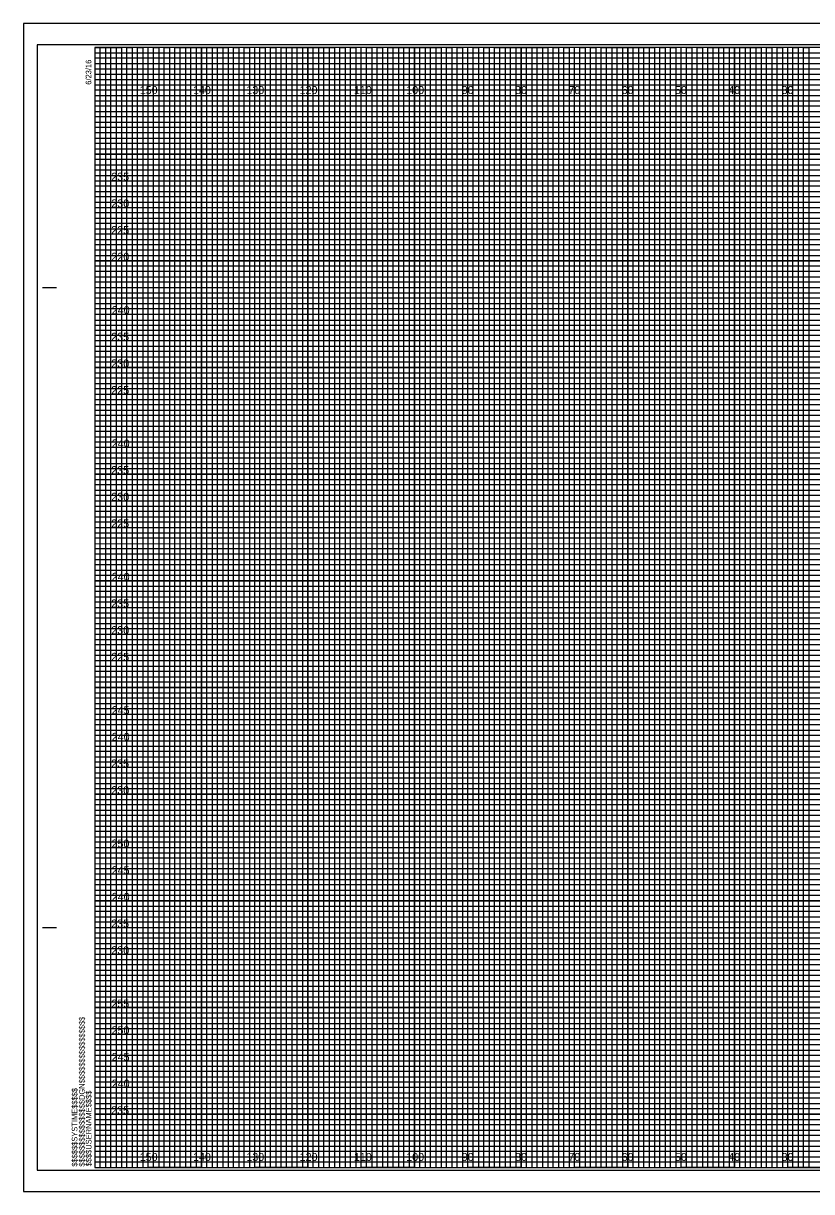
# Model space of a CAD drawing. Extents: x -13 to 323, y -5 to 434.
# Drawn here: x -13.4 to 134.5, y -4.5 to 214.5 of the extents above; entities that cross this region are included whole.
import ezdxf

# ---------------------------------------------------------------- set-up
doc = ezdxf.new("R2010")
doc.units = 0
for name, color, linetype in [('Prop XS Elevation Labels', 7, 'Continuous'), ('Prop XS Offset Labels', 7, 'Continuous'), ('Sheet Cross Section CELL', 7, 'Continuous'), ('Sheet Cross Section Grid Major CELL', 7, 'Continuous'), ('Sheet Cross Section Grid Middle CELL', 7, 'Continuous'), ('Sheet Cross Section Grid Minor 1 CELL', 7, 'Continuous'), ('Sheet Cross Section Grid Minor 2 CELL', 7, 'Continuous'), ('Sheet Cutting Line CELL', 7, 'Continuous'), ('Sheet DOT Grid CELL', 7, 'Continuous'), ('Sheet Plot Border Inside CELL', 7, 'Continuous'), ('Sheet Plot Border Outside CELL', 7, 'Continuous')]:
    doc.layers.add(name, color=color, linetype=linetype)

msp = doc.modelspace()

# ---------------------------------------------------------------- linework, layer by layer
at = {"layer": 'Sheet Cross Section CELL'}
for p, q in [((-9.8, 165), (-7.3, 165)), ((-9.7, 165), (-7.2, 165)), ((-9.8, 45), (-7.3, 45)), ((-9.7, 45), (-7.2, 45)), ((0, 0), (0, 0)), ((0, 0), (0, 0)), ((0, 0), (0, 0)), ((0, 0), (0, 0)), ((0, 0), (0, 0)), ((0, 0), (0, 0)), ((0, 0), (0, 0))]:
    msp.add_line(p, q, dxfattribs=at)
msp.add_lwpolyline([(320, 210), (0, 210), (0, 0), (320, 0)], close=True, dxfattribs=at)
at = {"layer": 'Sheet Cross Section Grid Major CELL'}
for p, q in [((10, 210), (0, 210)), ((10, 0), (10, 210)), ((30, 210), (20, 210)), ((20, 210), (20, 0)), ((30, 0), (30, 210)), ((50, 210), (40, 210)), ((40, 210), (40, 0)), ((50, 0), (50, 210)), ((70, 210), (60, 210)), ((60, 210), (60, 0)), ((70, 0), (70, 210)), ((90, 210), (80, 210)), ((80, 210), (80, 0)), ((90, 0), (90, 210)), ((110, 210), (100, 210)), ((100, 210), (100, 0)), ((110, 0), (110, 210)), ((130, 210), (120, 210)), ((120, 210), (120, 0)), ((130, 0), (130, 210)), ((20, 0), (10, 0)), ((40, 0), (30, 0)), ((60, 0), (50, 0)), ((80, 0), (70, 0)), ((100, 0), (90, 0)), ((120, 0), (110, 0)), ((140, 0), (130, 0))]:
    msp.add_line(p, q, dxfattribs=at)
for points in [[(0, 200), (320, 200), (320, 190), (0, 190)], [(0, 180), (320, 180), (320, 170), (0, 170)], [(0, 160), (320, 160), (320, 150), (0, 150)], [(0, 140), (320, 140), (320, 130), (0, 130)], [(0, 120), (320, 120), (320, 110), (0, 110)], [(0, 100), (320, 100), (320, 90), (0, 90)], [(0, 80), (320, 80), (320, 70), (0, 70)], [(0, 60), (320, 60), (320, 50), (0, 50)], [(0, 40), (320, 40), (320, 30), (0, 30)], [(0, 20), (320, 20), (320, 10), (0, 10)]]:
    msp.add_lwpolyline(points, dxfattribs=at)
at = {"layer": 'Sheet Cross Section Grid Middle CELL'}
for points in [[(0, 210), (5, 210), (5, 0), (15, 0), (15, 210), (25, 210), (25, 0), (35, 0), (35, 210), (45, 210), (45, 0), (55, 0), (55, 210), (65, 210), (65, 0), (75, 0), (75, 210), (85, 210), (85, 0), (95, 0), (95, 210), (105, 210), (105, 0), (115, 0), (115, 210), (125, 210), (125, 0), (135, 0)], [(0, 205), (275, 205)], [(0, 185), (320, 185), (320, 195), (0, 195)], [(0, 165), (320, 165), (320, 175), (0, 175)], [(0, 145), (320, 145), (320, 155), (0, 155)], [(0, 125), (320, 125), (320, 135), (0, 135)], [(0, 105), (320, 105), (320, 115), (0, 115)], [(0, 85), (320, 85), (320, 95), (0, 95)], [(0, 65), (320, 65), (320, 75), (0, 75)], [(0, 45), (320, 45), (320, 55), (0, 55)], [(0, 25), (320, 25), (320, 35), (0, 35)], [(0, 5), (320, 5), (320, 15), (0, 15)]]:
    msp.add_lwpolyline(points, dxfattribs=at)
at = {"layer": 'Sheet Cross Section Grid Minor 1 CELL'}
for p, q in [((0, 209), (260, 209)), ((260, 207.98), (0, 207.98)), ((0, 207.98), (0, 207)), ((0, 207), (260, 207)), ((260, 205.89), (0, 205.89)), ((0, 205.89), (0, 204)), ((0, 204), (320, 204))]:
    msp.add_line(p, q, dxfattribs=at)
for points in [[(0, 203), (270, 203), (320, 203), (320, 202), (0, 202)], [(0, 201), (320, 201), (320, 199), (0, 199)], [(0, 198), (320, 198), (320, 197), (0, 196.98)], [(0, 196), (320, 196), (320, 194), (0, 194)], [(0, 193), (320, 193), (320, 192), (0, 192)], [(0, 191), (320, 191), (320, 189), (0, 189)], [(0, 188), (320, 188), (320, 187), (0, 187)], [(0, 186), (320, 186), (320, 184), (0, 184)], [(0, 183), (320, 183), (320, 182), (0, 182)], [(0, 181), (320, 181), (320, 179), (0, 179)], [(0, 178), (320, 178), (320, 177), (0, 177)], [(0, 176), (320, 176), (320, 173.95), (320, 173), (320, 172), (0, 172)], [(0, 174), (320, 174), (320, 173), (0, 173)], [(0, 171), (320, 171), (320, 169), (0, 169.03)], [(0, 169.03), (320, 169), (320, 168), (0, 168)], [(0, 167), (320, 167), (320, 166), (0, 166)], [(0, 164), (320, 164), (320, 163), (0, 163)], [(0, 162), (320, 162), (320, 161), (0, 161)], [(-0.07, 158.89), (320, 158.89), (320, 157.88), (-0.07, 157.88)], [(0, 157), (320, 157), (320, 156), (0, 156)], [(0, 154), (320, 154), (320, 153), (0, 153)], [(0, 152), (320, 152), (320, 151), (0, 151)], [(0, 149), (320, 149), (320, 148), (0, 148)], [(0, 147), (320, 147), (320, 146), (0, 146)], [(0, 144), (320, 144), (320, 143), (0, 143)], [(0, 142), (320, 142), (320, 141), (0, 141)], [(0, 139), (320, 139), (319.99, 137.98), (0, 138)], [(0, 137), (320, 137), (320, 136), (0, 136)], [(0, 134), (320, 134), (320, 133), (0, 133)], [(0, 132), (320, 132), (320, 131), (0, 131)], [(0, 129), (320, 129), (320, 128), (0, 128)], [(0, 127), (320, 127), (320, 126), (0, 126)], [(0, 124), (320, 124), (320, 123), (0, 123)], [(0, 122), (320, 122), (320, 121), (0, 121)], [(0, 119), (320, 119), (320, 118), (0, 118)], [(0, 116.99), (320.07, 116.91), (320, 116), (0, 116)], [(0, 114), (320, 114), (320, 113), (0, 113)], [(0, 112), (320, 112), (320, 111), (0, 111)], [(0, 109), (320, 109), (320, 108), (0, 108)], [(0, 107), (320, 107), (320, 106), (0, 106)], [(0, 104), (320, 104), (320, 103), (0, 103)], [(0, 102), (320, 102), (320, 101), (0, 101)], [(0, 99), (320, 99), (320, 98), (0, 98)], [(0, 97), (320, 97), (320, 96), (0, 96)], [(0, 94), (320, 94), (320, 93), (0, 93)], [(0, 92), (320, 92), (320, 91), (0, 91)], [(0, 89), (320, 89), (320, 88), (0, 88)], [(0, 87), (320, 87), (320, 86), (0, 86)], [(0, 84), (320, 84), (320, 83), (0, 83)], [(0, 82), (320, 82), (320, 81), (0, 81)], [(0, 79), (320, 79), (319.99, 77.98), (0, 78)], [(0, 77), (320, 77), (320, 76), (0, 76)], [(0, 74), (320, 74), (320, 73), (0, 73)], [(0, 72), (320, 72), (320, 71), (0, 71)], [(0, 69), (320, 69), (320, 68), (0, 68)], [(0, 67), (320, 67), (320, 66), (0, 66)], [(0, 64), (320, 64), (320, 63), (0, 63)], [(0, 62), (320, 62), (320, 61), (0, 61)], [(0, 59), (320, 59), (320, 58), (0, 58)], [(0, 56.99), (320.07, 56.91), (320, 56), (0, 56)], [(0, 54), (320, 54), (320, 53), (0, 53)], [(0, 52), (320, 52), (320, 51), (0, 51)], [(0, 49), (320, 49), (320, 48), (0, 48)], [(0, 47), (320, 47), (320, 46), (0, 46)], [(0, 44), (320, 44), (320, 43), (0, 43)], [(0, 42), (320, 42), (320, 41), (0, 41)], [(0, 39), (320, 39), (320, 38), (0, 38)], [(0, 37), (320, 37), (320, 36), (0, 36)], [(0, 34), (320, 34), (320, 33), (0, 33)], [(0, 32), (320, 32), (320, 31), (0, 31)], [(0, 29), (320, 29), (320, 28), (0, 28)], [(0, 27), (320, 27), (320, 26), (0, 26)], [(0, 24), (320, 24), (320, 23), (0, 23)], [(0, 22), (320, 22), (320, 21), (0, 21)], [(0, 19), (320, 19), (320, 18), (0, 18)], [(0, 17), (320, 17), (320, 16), (0, 16)], [(0, 14), (320, 14), (320, 13), (0, 13)], [(0, 12), (320, 12), (320, 11), (0, 11)], [(0, 9), (320, 9), (320, 8), (0, 8)], [(0, 7), (320, 7), (320, 6), (0, 6)], [(0, 4), (320, 4), (320, 3), (0, 3)], [(0, 2), (320, 2), (320, 1), (0, 1)]]:
    msp.add_lwpolyline(points, dxfattribs=at)
at = {"layer": 'Sheet Cross Section Grid Minor 2 CELL'}
for points in [[(0, 0), (1, 0), (1, 210), (2, 210), (2, 0)], [(2, 0), (3, 0), (3, 210), (4, 210), (4, 0)], [(5, 0), (6, 0), (6, 210), (7, 210), (7, 0)], [(7, 0), (8, 0), (8, 210), (9, 210), (9, 0)], [(10, 0), (11, 0), (11, 210), (12, 210), (12, 0)], [(12, 0), (13, 0), (13, 210), (14, 210), (14, 0)], [(15, 0), (16, 0), (16, 210), (17, 210), (17, 0)], [(17, 0), (18, 0), (18, 210), (19, 210), (19, 0)], [(20, 0), (21, 0), (21, 210), (22, 210), (22, 0)], [(22, 0), (23, 0), (23, 210), (24, 210), (24, 0)], [(25, 0), (26, 0), (26, 210), (27, 210), (27, 0)], [(27, 0), (28, 0), (28, 210), (29, 210), (29, 0)], [(30, 0), (31, 0), (31, 210), (32, 210), (32, 0)], [(32, 0), (33, 0), (33, 210), (34, 210), (34, 0)], [(35, 0), (36, 0), (36, 210), (37, 210), (37, 0)], [(37, 0), (38, 0), (38, 210), (39, 210), (39, 0)], [(40, 0), (41, 0), (41, 210), (42, 210), (42, 0)], [(42, 0), (43, 0), (43, 210), (44, 210), (44, 0)], [(45, 0), (46, 0), (46, 210), (47, 210), (47, 0)], [(47, 0), (48, 0), (48, 210), (49, 210), (49, 0)], [(50, 0), (51, 0), (51, 210), (52, 210), (52, 0)], [(52, 0), (53, 0), (53, 210), (54, 210), (54, 0)], [(55, 0), (56, 0), (56, 210), (57, 210), (57, 0)], [(57, 0), (58, 0), (58, 210), (59, 210), (59, 0)], [(60, 0), (61, 0), (61, 210), (62, 210), (62, 0)], [(62, 0), (63, 0), (63, 210), (64, 210), (64, 0)], [(65, 0), (66, 0), (66, 210), (67, 210), (67, 0)], [(67, 0), (68, 0), (68, 210), (69, 210), (69, 0)], [(70, 0), (71, 0), (71, 210), (72, 210), (72, 0)], [(72, 0), (73, 0), (73, 210), (74, 210), (74, 0)], [(75, 0), (76, 0), (76, 210), (77, 210), (77, 0)], [(77, 0), (78, 0), (78, 210), (79, 210), (79, 0)], [(80, 0), (81, 0), (81, 210), (82, 210), (82, 0)], [(82, 0), (83, 0), (83, 210), (84, 210), (84, 0)], [(85, 0), (86, 0), (86, 210), (87, 210), (87, 0)], [(87, 0), (88, 0), (88, 210), (89, 210), (89, 0)], [(90, 0), (91, 0), (91, 210), (92, 210), (92, 0)], [(92, 0), (93, 0), (93, 210), (94, 210), (94, 0)], [(95, 0), (96, 0), (96, 210), (97, 210), (97, 0)], [(97, 0), (98, 0), (98, 210), (99, 210), (99, 0)], [(100, 0), (101, 0), (101, 210), (102, 210), (102, 0)], [(102, 0), (103, 0), (103, 210), (104, 210), (104, 0)], [(105, 0), (106, 0), (106, 210), (107, 210), (107, 0)], [(107, 0), (108, 0), (108, 210), (109, 210), (109, 0)], [(110, 0), (111, 0), (111, 210), (112, 210), (112, 0)], [(112, 0), (113, 0), (113, 210), (114, 210), (114, 0)], [(115, 0), (116, 0), (116, 210), (117, 210), (117, 0)], [(117, 0), (118, 0), (118, 210), (119, 210), (119, 0)], [(120, 0), (121, 0), (121, 210), (122, 210), (122, 0)], [(122, 0), (123, 0), (123, 210), (124, 210), (124, 0)], [(125, 0), (126, 0), (126, 210), (127, 210), (127, 0)], [(127, 0), (128, 0), (128, 210), (129, 210), (129, 0)], [(130, 0), (131, 0), (131, 210), (132, 210), (132, 0)], [(132, 0), (133, 0), (133, 210), (134, 210), (134, 0)]]:
    msp.add_lwpolyline(points, dxfattribs=at)
at = {"layer": 'Sheet Cutting Line CELL'}
for p, q in [((323.3, 214.5), (-13.4, 214.5)), ((-13.4, 214.5), (-13.4, -4.5)), ((-13.4, -4.5), (323.3, -4.5))]:
    msp.add_line(p, q, dxfattribs=at)
at = {"layer": 'Sheet DOT Grid CELL'}
for p, q in [((10, 0), (10, 210)), ((20, 0), (20, 210)), ((30, 0), (30, 210)), ((40, 0), (40, 210)), ((50, 0), (50, 210)), ((60, 0), (60, 210)), ((70, 0), (70, 210)), ((80, 0), (80, 210)), ((90, 0), (90, 210)), ((100, 0), (100, 210)), ((110, 0), (110, 210)), ((120, 0), (120, 210)), ((130, 0), (130, 210)), ((0, 200), (320, 200)), ((0, 190), (320, 190)), ((0, 180), (320, 180)), ((0, 170), (320, 170)), ((0, 160), (320, 160)), ((0, 150), (320, 150)), ((0, 140), (320, 140)), ((0, 130), (320, 130)), ((0, 120), (320, 120)), ((0, 110), (320, 110)), ((0, 100), (320, 100)), ((0, 90), (320, 90)), ((0, 80), (320, 80)), ((0, 70), (320, 70)), ((0, 60), (320, 60)), ((0, 50), (320, 50)), ((0, 40), (320, 40)), ((0, 30), (320, 30)), ((0, 20), (320, 20)), ((0, 10), (320, 10))]:
    msp.add_line(p, q, dxfattribs=at)
at = {"layer": 'Sheet Plot Border Inside CELL'}
msp.add_lwpolyline([(-10.8, -0.5), (322.4, -0.5), (322.4, 210.5), (-10.8, 210.5)], close=True, dxfattribs=at)
at = {"layer": 'Sheet Plot Border Outside CELL'}
msp.add_lwpolyline([(-13.4, -4.5), (323.3, -4.5), (323.3, 214.5), (-13.4, 214.5)], close=True, dxfattribs=at)

# ---------------------------------------------------------------- texts
at = {"layer": 'Prop XS Elevation Labels'}
for s, p in [('235', (3.09, 185)), ('230', (3.11, 180)), ('225', (3.1, 175)), ('220', (3.12, 170)), ('240', (3.19, 160)), ('235', (3.09, 155)), ('230', (3.11, 150)), ('225', (3.1, 145)), ('240', (3.19, 135)), ('235', (3.09, 130)), ('230', (3.11, 125)), ('225', (3.1, 120)), ('240', (3.19, 110)), ('235', (3.09, 105)), ('230', (3.11, 100)), ('225', (3.1, 95)), ('245', (3.18, 85)), ('240', (3.19, 80)), ('235', (3.09, 75)), ('230', (3.11, 70)), ('250', (3.15, 60)), ('245', (3.18, 55)), ('240', (3.19, 50)), ('235', (3.09, 45)), ('230', (3.11, 40)), ('255', (3.13, 30)), ('250', (3.15, 25)), ('245', (3.18, 20)), ('240', (3.19, 15)), ('235', (3.09, 10))]:
    msp.add_text(s, height=1.5, dxfattribs=at).set_placement(p)
at = {"layer": 'Prop XS Offset Labels'}
for s, p in [('150', (8.44, 201.25)), ('140', (18.44, 201.25)), ('130', (28.44, 201.25)), ('120', (38.44, 201.25)), ('110', (48.62, 201.25)), ('100', (58.44, 201.25)), ('90', (68.86, 201.25)), ('80', (78.86, 201.25)), ('70', (88.86, 201.25)), ('60', (98.86, 201.25)), ('50', (108.86, 201.25)), ('40', (118.86, 201.25)), ('30', (128.86, 201.25)), ('150', (8.44, 1.25)), ('140', (18.44, 1.25)), ('130', (28.44, 1.25)), ('120', (38.44, 1.25)), ('110', (48.62, 1.25)), ('100', (58.44, 1.25)), ('90', (68.86, 1.25)), ('80', (78.86, 1.25)), ('70', (88.86, 1.25)), ('60', (98.86, 1.25)), ('50', (108.86, 1.25)), ('40', (118.86, 1.25)), ('30', (128.86, 1.25))]:
    msp.add_text(s, height=1.5, dxfattribs=at).set_placement(p)
at = {"layer": 'Sheet Cross Section CELL'}
for s, p in [('6/23/16', (-0.65, 203)), ('$$$$$$$$$$$$$$$$DGN$$$$$$$$$$$$$$$$', (-1.88, 0.18)), ('$$$$$$SYSTIME$$$$$', (-3.26, 0.18)), ('$$$$USERNAME$$$$', (-0.62, 0.23))]:
    msp.add_text(s, height=1.05, rotation=90, dxfattribs=at).set_placement(p)

doc.saveas('drawing.dxf')
